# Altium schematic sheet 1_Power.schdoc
size 309 x 223 mm; Symbol: Sheet-Symbol_A4; Device: Sheet-Symbol_A4; @Project Name: Digital_Watch_V01; @Page Count: 3; @Update Date: 2024-12-05; @Create Date: 2024-12-05; @Schematic Name: D-Watch_Sch_v1.3; @Page No: 1; @Page Name: Power; Company: EasyEDA.com; Reviewed: EasyEDA; Version: V0.1; Page Size: A4; Part Number: JLCPCB-002; Drawn: EasyEDA; @Board Name: D-Watch_Board_v1.3; @Create Time: 20:28:54; @Update Time: 21:28:54
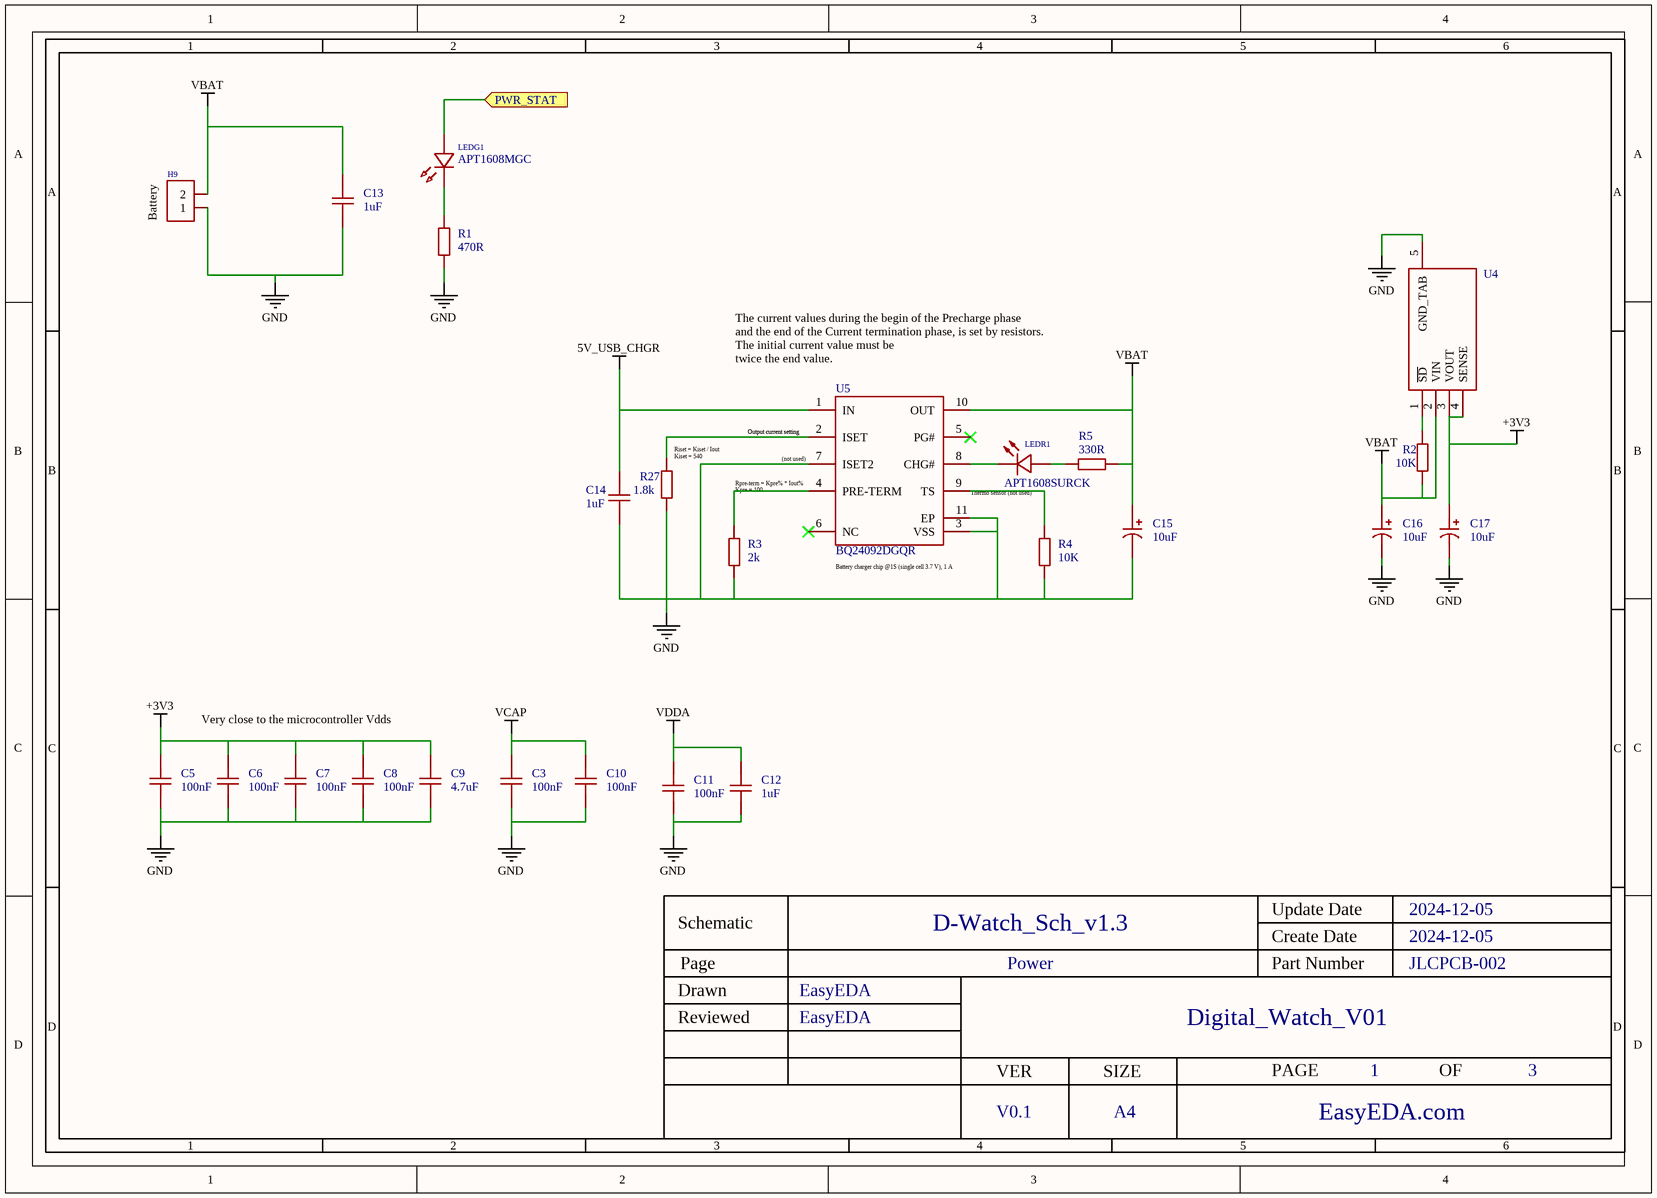
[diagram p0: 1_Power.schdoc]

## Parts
C3  100nF  [C0603]  (value not drawn)
C5  100nF  [C0603]  (value not drawn)
C6  100nF  [C0603]  (value not drawn)
C7  100nF  [C0603]  (value not drawn)
C8  100nF  [C0603]  (value not drawn)
C9  4.7uF  [C0603]  (value not drawn)
C10  100nF  [C0603]  (value not drawn)
C11  100nF  [C0603]  (value not drawn)
C12  1uF  [C0603]  (value not drawn)
C13  1uF  [C0603]  (value not drawn)
C14  1uF  [C0603]  (value not drawn)
C15  10uF  [CAP-SMD_L1.6-W0.8-RD]  (value not drawn)
C16  10uF  [CAP-SMD_L1.6-W0.8-RD]  (value not drawn)
C17  10uF  [CAP-SMD_L1.6-W0.8-RD]  (value not drawn)
H9  HDR-F_2.54_1x2P  [HDR-TH_2P-P2.54-V-F]  (value not drawn)
LEDG1  APT1608MGC  [LED-SMD_L1.6-W0.8-RD]  (value not drawn)
LEDR1  APT1608SURCK  [LED0603-RD]  (value not drawn)
R1  470R  [R0603]  (value not drawn)
R2  10K  [R0603]  (value not drawn)
R3  2k  [R0603]  (value not drawn)
R4  10K  [R0603]  (value not drawn)
R5  330R  [R0603]  (value not drawn)
R27  1.8k  [R0603]  (value not drawn)
U4  LP3874EMP-3.3_NOPB_  [SOT150P700X180-5N]  (value not drawn)
U5  BQ24092DGQR  [MSOP-10_L3.0-W3.0-P0.50-LS5.0-BL-EP]  (value not drawn)

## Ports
PWR_STAT (in)

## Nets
5V_USB_CHGR: C14.2 U5.1(IN)
+3V3: C5.1 C6.1 C7.1 C8.1 C9.1 C17.1 U4.3(VOUT) U4.4(SENSE)
GND: C3.2 C5.2 C6.2 C7.2 C8.2 C9.2 C10.2 C11.2 C12.1 C13.1 C14.1 C15.2 C16.2 C17.2 H9.1 R1.1 R3.1 R4.2 R27.1 U4.5(GND_TAB) U5.3(VSS) U5.7(ISET2) U5.11(EP)
VBAT: C13.2 C15.1 C16.1 H9.2 R2.1 R5.1 U4.2(VIN) U5.10(OUT)
VCAP: C3.1 C10.1
VDDA: C11.1 C12.2
PWR_STAT: LEDG1.2(A) ; port PWR_STAT
NetLEDG1_1: LEDG1.1(K) R1.2
NetLEDR1_1: LEDR1.1(K) U5.8(CHG#)
NetLEDR1_2: LEDR1.2(A) R5.2
NetR2_2: R2.2 U4.1(~{SD})
NetR3_2: R3.2 U5.4(PRE-TERM)
NetR4_1: R4.1 U5.9(TS)
NetR27_2: R27.2 U5.2(ISET)

Not connected (* = marked no-connect by the designer): U5 5(PG#)* 6(NC)*

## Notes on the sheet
- (near H9) Battery
- (near U5) The current values during the begin of the Precharge phase
  and the end of the Current termination phase, is set by resistors.
  The initial current value must be
  twice the end value.
- (near R3) Riset = Kiset / Iout
  Kiset = 540
- Rpre-term = Kpre% * Iout%
  Kpre = 100
- (near U5) Output current setting
- (near U5) (not used)
- Thermo sensor (not used)
- (near U5) Battery charger chip @1S (single cell 3.7 V), 1 A
- Very close to the microcontroller Vdds

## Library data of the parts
C3 C5-C8 C10 C11 = GCJ188R71C104KA01D: Capacitance: Tolerance:±10% Tolerance:±10% Voltage Rated: Temperature Coefficient:; Manufacturer: muRata(村田); Add into BOM: yes; Tolerance: ±10%
C9 = GCJ188C70J475KE02D: Capacitance: Tolerance:±10% Tolerance:±10% Voltage Rated: Temperature Coefficient:; Manufacturer: muRata(村田); Add into BOM: yes; Tolerance: ±10%
C12-C14 = CC0603KRX7R5BB105: Capacitance: Tolerance:±10% Tolerance:±10% Voltage Rated: Temperature Coefficient:; Manufacturer: YAGEO(国巨); Add into BOM: yes; Tolerance: ±10%
C15-C17 = T58MM106M6R3C0300: Capacitance: Tolerance:±20% Tolerance:±20% Rated Voltage: Leakage Current(DCL):- Ripple Current:- Equivalent Series Resistance(ESR):300mΩ@100kHz Operating Temperature:-55℃~+105℃ Operating Temperature:-55℃~+105℃; Manufacturer: VISHAY(威世); Add into BOM: yes; Tolerance: ±20%
H9 = HDR-F_2.54_1x2P: Manufacturer: BOOMELE(博穆精密); Manufacturer Part: 2.54-1*2P母; Symbol: Header-Female-2.54_1x2; Convert to PCB: yes
LEDG1 = APT1608MGC: Emitted Color:Emerald Forward Voltage (VF):2.1V Forward Voltage (VF):2.1V Forward Current:20mA Dominant Wavelength:570nm Dominant Wavelength:570nm Peak Wavelength:574nm Lens Color:无色透明透镜 Luminous Intensity:60mcd Luminous Intensity:60mcd Viewing Angle:120°; Manufacturer: Kingbright; Add into BOM: yes; Forward Voltage (VF): 2.1V; Forward Current: 20mA; Dominant Wavelength: 570nm; Peak Wavelength: 574nm; Lens Color: 无色透明透镜; Luminous Intensity: 60mcd; Viewing Angle: 120°
LEDR1 = APT1608SURCK: Emitted Color:Red Forward Voltage (VF):1.95V Forward Voltage (VF):1.95V Forward Current:20mA Dominant Wavelength:630nm Dominant Wavelength:630nm Peak Wavelength:645nm Lens Color:无色透明透镜 Luminous Intensity:80mcd Luminous Intensity:80mcd Viewing Angle:120°; Manufacturer: Kingbright; Add into BOM: yes; Emitted Color: Red; Forward Voltage (VF): 1.95V; Forward Current: 20mA; Dominant Wavelength: 630nm; Peak Wavelength: 645nm; Lens Color: 无色透明透镜; Luminous Intensity: 80mcd; Viewing Angle: 120°
R1-R5 R27 = Res_0603: Symbol: Res; Convert to PCB: yes
U4 = LP3874EMP-3.3_NOPB_: Add into BOM: yes
U5 = BQ24092DGQR: Supply Voltage:6.45V Supply Voltage:6.45V Maximum Charge Current:1A Type of Battery:锂离子/Polymer Number of Cells:1 Number of Cells:1 Operating Temperature:0℃~+125℃ Operating Temperature:0℃~+125℃; Manufacturer: TI(德州仪器); Add into BOM: yes; Supply Voltage: 6.45V; Maximum Charge Current: 1A; Number of Cells: 1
